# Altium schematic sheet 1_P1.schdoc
size 307 x 218 mm; Symbol: Drawing-Symbol_A4; Device: Drawing-Symbol_A4; Company: AtomicBool; Version: V1.0; Page Size: A4; @Project Name: PocketEPD; @Page Count: 1; @Update Date: 2025-11-20; @Create Date: 2025-10-21; @Schematic Name: Main_Schematic; @Page No: 1; @Page Name: P1; @Create Time: 15:51:57; @Update Time: 02:26:05; Width: 1170; Height: 825; Region Start: 1; X Region Count: 6; Y Region Count: 4; Blade Width: 10; Title Block Position: 3; @Board Name: PockEINK
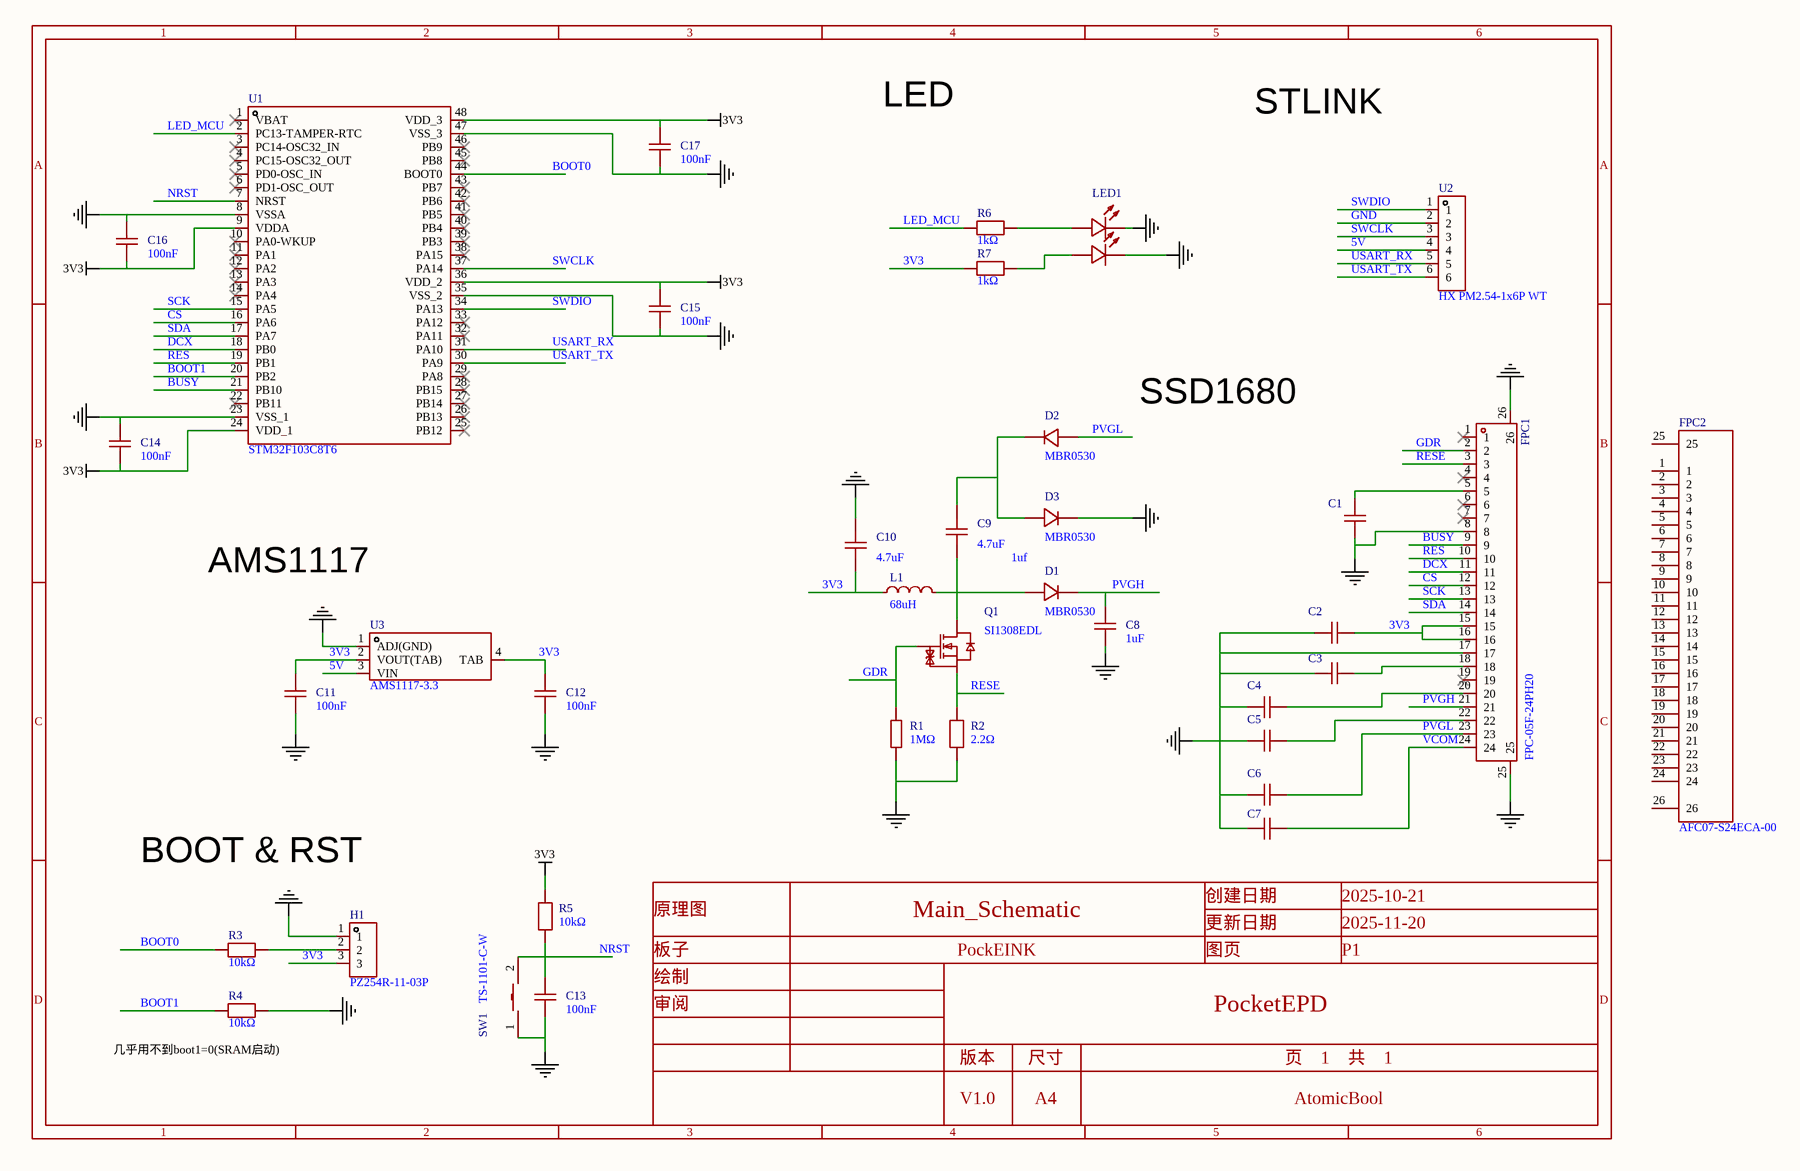
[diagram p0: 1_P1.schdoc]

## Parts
C1  1uF  [C1206]  (value not drawn)
C2  1uF  [C1206]  (value not drawn)
C3  1uF  [C1206]  (value not drawn)
C4  1uF  [C1206]  (value not drawn)
C5  1uF  [C1206]  (value not drawn)
C6  1uF  [C1206]  (value not drawn)
C7  1uF  [C1206]  (value not drawn)
C8  1uF  [C1206]
C9  4.7uF  [C1206]
C10  4.7uF  [C1206]
C11  100nF  [C1206]
C12  100nF  [C1206]
C13  100nF  [C1206]
C14  100nF  [C1206]
C15  100nF  [C1206]
C16  100nF  [C1206]
C17  100nF  [C1206]
D1  MBR0530  [SOD-123_L2.8-W1.8-LS3.7-RD]
D2  MBR0530  [SOD-123_L2.8-W1.8-LS3.7-RD]
D3  MBR0530  [SOD-123_L2.8-W1.8-LS3.7-RD]
FPC1  FPC-05F-24PH20  [FPC-SMD_24P-P0.50_FPC-05F-24PH20]
FPC2  AFC07-S24ECA-00  [FPC-SMD_AFC07-S24ECA-00]
H1  PZ254R-11-03P  [HDR-TH_3P-P2.54-H-M-W10.4]
L1  68uH  [IND-SMD_L4.0-W4.0_FNR40XXS]
LED1  TJ-S3227SW1TCGLC2R6B-A5  [LED-SMD_4P-L3.2-W2.7_PD15-22C]  (value not drawn)
Q1  SI1308EDL  [SOT-323-3_L2.0-W1.3-P1.30-LS2.1-BR]
R1  1MΩ  [R1206]
R2  2.2Ω  [R1206]
R3  10kΩ  [R1206]
R4  10kΩ  [R1206]
R5  10kΩ  [R1206]
R6  1kΩ  [R1206]
R7  1kΩ  [R1206]
SW1  TS-1101-C-W  [SW-SMD_L6.0-W3.3-LS8.0]
U1  STM32F103C8T6  [LQFP-48_L7.0-W7.0-P0.50-LS9.0-BL]
U2  HX PM2.54-1x6P WT  [HDR-SMD_6P-P2.54-H-F-W11.7]
U3  AMS1117-3.3  [SOT-223-4_L6.5-W3.5-P2.30-LS7.0-BR]

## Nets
3V3: C2.1 C10.1 C11.2 C12.2 C14.2 C15.2 C16.2 C17.1 FPC1.15 FPC1.16 H1.3 L1.1 R5.2 R7.1 U1.9(VDDA) U1.24(VDD_1) U1.36(VDD_2) U1.48(VDD_3) U3.2(VOUT(TAB)) U3.4(TAB)
GND: C1.1 C2.2 C3.2 C4.2 C5.2 C6.2 C7.2 C8.1 C10.2 C11.1 C12.1 C13.2 C14.1 C15.1 C16.1 C17.2 D3.1(C) FPC1.8 FPC1.17 FPC1.25 FPC1.26 H1.1 LED1.1(C) LED1.4(C) R1.1 R2.1 R4.2 SW1.1 U1.8(VSSA) U1.23(VSS_1) U1.35(VSS_2) U1.47(VSS_3) U2.2 U3.1(ADJ(GND))
5V: U2.4 U3.3(VIN)
BOOT0: R3.1 U1.44(BOOT0)
BOOT1: R4.1 U1.20(PB2)
BUSY: FPC1.9 U1.21(PB10)
CS: FPC1.12 U1.16(PA6)
DCX: FPC1.11 U1.18(PB0)
GDR: FPC1.2 Q1.1(G) R1.2
LED_MCU: R6.1 U1.2(PC13-TAMPER-RTC)
NRST: C13.1 R5.1 SW1.2 U1.7(NRST)
PVGH: C8.2 D1.1(C) FPC1.21
PVGL: C6.1 D2.2(A) FPC1.23
RES: FPC1.10 U1.19(PB1)
RESE: FPC1.3 Q1.2(S) R2.2
SCK: FPC1.13 U1.15(PA5)
SDA: FPC1.14 U1.17(PA7)
SWCLK: U1.37(PA14) U2.3
SWDIO: U1.34(PA13) U2.1
USART_RX: U1.31(PA10) U2.5
USART_TX: U1.30(PA9) U2.6
VCOM: C7.1 FPC1.24
NetC1_2: C1.2 FPC1.5
NetC3_1: C3.1 FPC1.18
NetC4_1: C4.1 FPC1.20
NetC5_1: C5.1 FPC1.22
NetC9_1: C9.1 D1.2(A) L1.2 Q1.3(D)
NetC9_2: C9.2 D2.1(C) D3.2(A)
NetH1_2: H1.2 R3.2
NetLED1_2: LED1.2(A) R7.2
NetLED1_3: LED1.3(A) R6.2

Not connected (* = marked no-connect by the designer): FPC1 1* 4* 6* 7* 19*; FPC2 1 2 3 4 5 6 7 8 9 10 11 12 13 14 15 16 17 18 19 20 21 22 23 24 25 26; U1 1(VBAT)* 3(PC14-OSC32_IN)* 4(PC15-OSC32_OUT)* 5(PD0-OSC_IN)* 6(PD1-OSC_OUT)* 10(PA0-WKUP)* 11(PA1)* 12(PA2)* 13(PA3)* 14(PA4)* 22(PB11)* 25(PB12)* 26(PB13)* 27(PB14)* 28(PB15)* 29(PA8)* 32(PA11)* 33(PA12)* 38(PA15)* 39(PB3)* 40(PB4)* 41(PB5)* 42(PB6)* 43(PB7)* 45(PB8)* 46(PB9)*

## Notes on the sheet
- LED
- STLINK
- SSD1680
- AMS1117
- 1uf
- BOOT & RST
- (near R4) 几乎用不到boot1=0(SRAM启动)

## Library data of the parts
C1-C8 = CL31B105KAHNNNE: Manufacturer: SAMSUNG(三星); Add into BOM: yes; Tolerance: ±10%; Voltage Rating: 25V; Temperature Coefficient: X7R
C9 C10 = 1206B475K250NT: Manufacturer: FH(风华); Add into BOM: yes; Tolerance: ±10%; Voltage Rating: 25V; Temperature Coefficient: X7R
C11-C17 = CL31B104KCFNNNE: Manufacturer: SAMSUNG(三星); Add into BOM: yes; Tolerance: ±10%; Voltage Rating: 100V; Temperature Coefficient: X7R
D1-D3 = MBR0530_C77336: Manufacturer: CJ(江苏长电/长晶); Add into BOM: yes; Voltage - Forward(Vf@If): 550mV@500mA; Voltage - DC Reverse(Vr): 30V; Current - Rectified: 500mA; Reverse Leakage Current (Ir): 80uA@30V; Non-Repetitive Peak Forward Surge Current: 5.5A
FPC1 = FPC-05F-24PH20: Manufacturer: XUNPU(讯普); Add into BOM: yes; Locking Feature: 翻盖式; Number of Contacts: 24P; Pitch: 0.5mm; FFC, FCB Thickness: 0.3mm; Rated Voltage (Max): 50V; Current Rating (Max): 500mA
FPC2 = AFC07-S24ECA-00: Manufacturer: JS(钜硕电子); Add into BOM: yes; Locking Feature: 抽屉式; Number of Contacts: 24P; Pitch: 0.5mm; FFC, FCB Thickness: 0.3mm
H1 = PZ254R-11-03P: Manufacturer: XFCN(兴飞); Add into BOM: yes; Pin Structure: 1x3P; Pitch: 2.54mm; Circluar Pins/Square Pins: 方针
L1 = FNR4020S680MT: Manufacturer: cjiang(长江微电); Add into BOM: yes; Tolerance: ±20%; Current Rating: 500mA; Current - Saturation(Isat): 670mA; DC Resistance(DCR): 1.38Ω; Type: 磁胶屏蔽绕线合金电感
LED1 = TJ-S3227SW1TCGLC2R6B-A5: Manufacturer: TOGIALED(统佳); Add into BOM: yes; Illumination Color: 红色,蓝色; Voltage - Forward(Vf): 1.8V~2.4V；2.8V~3.4V; Power(Watts): 108mW；72mW; Forward Current: 20mA; Wavelength - Dominant: 620nm~630nm；460nm~470nm; Peak Wavelength: 460nm；630nm; Lens Color: 无色透明透镜; Luminous Intensity: 200mcd; Viewing Angle: 120°
Q1 = SI1308EDL: Manufacturer: TECH PUBLIC(台舟); Symbol: SI1308EDL_C7603347; Add into BOM: yes; Drain to Source Voltage: 30V; Current - Continuous Drain(Id): 1.4A; RDS(on): 150mΩ@4.5V,0.5A; Pd - Power Dissipation: 360mW; Gate Threshold Voltage (Vgs(th)): 1.5V; Input Capacitance(Ciss): 146pF@15V; Reverse Transfer Capacitance (Crss@Vds): 14.8pF@15V
R1 = FRC1206J105 TS: Manufacturer: FOJAN(富捷); Add into BOM: yes; Tolerance: ±5%; Power(Watts): 250mW; Voltage-Supply(Max): 200V; Temperature Coefficient: ±100ppm/℃
R2 = FRC1206J2R2 TS: Manufacturer: FOJAN(富捷); Add into BOM: yes; Tolerance: ±5%; Power(Watts): 250mW; Voltage-Supply(Max): 200V; Temperature Coefficient: ±200ppm/℃
R3-R5 = FRC1206J103 TS: Manufacturer: FOJAN(富捷); Add into BOM: yes; Tolerance: ±5%; Power(Watts): 250mW; Voltage-Supply(Max): 200V; Temperature Coefficient: ±100ppm/℃
R6 R7 = FRC1206J102 TS: Manufacturer: FOJAN(富捷); Add into BOM: yes; Tolerance: ±5%; Power(Watts): 250mW; Voltage-Supply(Max): 200V; Temperature Coefficient: ±100ppm/℃
SW1 = TS-1101-C-W: Manufacturer: XKB Connectivity(中国星坤); Add into BOM: yes; Circuit: 单刀单掷; Actuator Style: 矩形按钮; Operating Force: 260gf; Switch Length: 6mm; Switch Width: 3.6mm; Switch Height: 2.5mm; Strike Gundam: 不带; Contact Current: 50mA; Voltage Rating (DC): 12V; Actuator/Cap Color: 白色带淡绿; With Lamp: 无; Mechanical Life: 5万次
U1 = STM32F103C8T6: Manufacturer: ST(意法半导体); Add into BOM: yes; CPU Core: ARM-M3; CPU Maximum Speed: 72MHz; Program Storage Size: 64KB; Program Memory Type: FLASH; Number of I/O: 37; ADC (Bit): 12bit; Voltage - Supply: 2V~3.6V
U2 = HX PM2.54-1x6P WT: Manufacturer: hanxia(韩下); Symbol: X6511FRS-06-C85D30; Add into BOM: yes; Holes Structure: 1x6P; Pitch: 2.54mm; Circular Hole / Square Hole: 方孔; Number of Positions: 6P; Current Rating: 3A; Voltage Rating (Max): 1kV; Holes Direction: 顶部; PIN Length: 3.2mm
U3 = AMS1117-3.3_C347222: Manufacturer: UMW(友台半导体); Add into BOM: yes; Output Type: 固定; Voltage - Supply: 12V; Output Voltage: 3.3V; Output Current: 1A; Power Supply Rejection Ratio (PSRR): 60dB@(120Hz); Voltage Dropout: 1.3V@(1A); Output Configuration: 正极; Number of Outputs: 1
